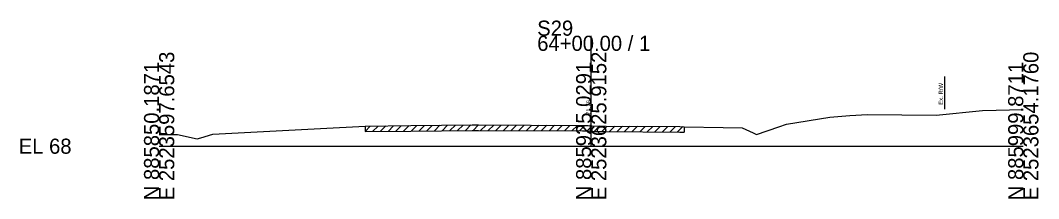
# Model space of a CAD drawing. Extents: x -26 to 163, y -10 to 4024.
# Drawn here: x -25.7 to 162.8, y 2990.3 to 3023.3 of the extents above; entities that cross this region are included whole.
import ezdxf

# ---------------------------------------------------------------- set-up
doc = ezdxf.new("R2010")
doc.units = 0
for name, color, linetype in [('RD_GPK_XS_Cell', 7, 'Continuous'), ('RD_XS_ExGround', 7, 'Continuous'), ('RD_XS_ExPaveRet', 7, 'Continuous'), ('RD_XS_ExRW', 7, 'Continuous'), ('RD_XS_TX_Elev_EX', 7, 'Continuous')]:
    doc.layers.add(name, color=color, linetype=linetype)

msp = doc.modelspace()

# ---------------------------------------------------------------- linework, layer by layer
at = {"layer": 'RD_GPK_XS_Cell'}
for p, q in [((80, 3000), (80, 3020.43)), ((0, 3000), (80, 3000)), ((80, 3000), (160, 3000))]:
    msp.add_line(p, q, dxfattribs=at)
at = {"layer": 'RD_XS_ExGround'}
for p, q in [((116.16, 3004.1), (124.21, 3005.35)), ((124.21, 3005.35), (127.89, 3005.69)), ((127.89, 3005.69), (131.15, 3005.84)), ((131.15, 3005.84), (143.87, 3005.72)), ((143.87, 3005.72), (152.42, 3006.61)), ((152.42, 3006.61), (160, 3006.81)), ((29.9, 3003.27), (38.13, 3003.69)), ((38.13, 3003.69), (46.62, 3003.8)), ((46.62, 3003.8), (57.97, 3003.93)), ((57.97, 3003.93), (59.13, 3003.93)), ((59.13, 3003.93), (78.42, 3003.85)), ((78.42, 3003.85), (79.46, 3003.84)), ((79.46, 3003.84), (79.89, 3003.76)), ((79.89, 3003.76), (80.2, 3003.75)), ((80.2, 3003.75), (82.68, 3003.73)), ((82.68, 3003.73), (96.43, 3003.62)), ((96.43, 3003.62), (97.21, 3003.61)), ((97.21, 3003.61), (104.44, 3003.49)), ((104.44, 3003.49), (107.92, 3003.4)), ((107.92, 3003.4), (110, 3002.45)), ((110.61, 3002.19), (114.74, 3003.6)), ((114.74, 3003.6), (116.16, 3004.1)), ((0, 3002.16), (1.97, 3002.17)), ((1.97, 3002.17), (2.28, 3002.18)), ((2.28, 3002.18), (3.4, 3002.18)), ((3.4, 3002.18), (7.06, 3001.36)), ((7.06, 3001.36), (7.7, 3001.52)), ((7.7, 3001.52), (9.96, 3002.21)), ((9.96, 3002.21), (29.9, 3003.27)), ((110, 3002.45), (110.61, 3002.19))]:
    msp.add_line(p, q, dxfattribs=at)
at = {"layer": 'RD_XS_ExPaveRet'}
for p, q in [((38.13, 3002.73), (39.1, 3003.71)), ((39.52, 3002.71), (40.54, 3003.73)), ((40.95, 3002.73), (41.97, 3003.74)), ((42.39, 3002.75), (43.4, 3003.76)), ((43.82, 3002.77), (44.83, 3003.78)), ((45.25, 3002.79), (46.27, 3003.8)), ((46.69, 3002.8), (47.7, 3003.82)), ((48.12, 3002.82), (49.13, 3003.83)), ((49.55, 3002.84), (50.56, 3003.85)), ((50.98, 3002.85), (51.99, 3003.87)), ((52.41, 3002.87), (53.42, 3003.88)), ((53.84, 3002.89), (54.85, 3003.9)), ((55.27, 3002.9), (56.28, 3003.92)), ((56.7, 3002.92), (57.71, 3003.93)), ((58.13, 3002.93), (59.12, 3003.93)), ((59.53, 3002.93), (60.53, 3003.92)), ((60.94, 3002.92), (61.94, 3003.92)), ((62.35, 3002.91), (63.35, 3003.91)), ((63.76, 3002.91), (64.76, 3003.9)), ((65.17, 3002.9), (66.16, 3003.9)), ((66.58, 3002.9), (67.57, 3003.89)), ((67.99, 3002.89), (68.98, 3003.89)), ((69.39, 3002.89), (70.39, 3003.88)), ((70.8, 3002.88), (71.8, 3003.88)), ((72.21, 3002.87), (73.21, 3003.87)), ((73.62, 3002.87), (74.62, 3003.86)), ((75.03, 3002.86), (76.02, 3003.86)), ((76.44, 3002.86), (77.43, 3003.85)), ((77.85, 3002.85), (78.84, 3003.85)), ((79.25, 3002.84), (80.16, 3003.75)), ((80.57, 3002.75), (81.56, 3003.74)), ((81.97, 3002.74), (82.97, 3003.73)), ((83.38, 3002.73), (84.37, 3003.72)), ((84.78, 3002.72), (85.77, 3003.71)), ((86.18, 3002.7), (87.18, 3003.7)), ((87.59, 3002.69), (88.58, 3003.69)), ((88.99, 3002.68), (89.98, 3003.67)), ((90.39, 3002.67), (91.38, 3003.66)), ((91.8, 3002.66), (92.79, 3003.65)), ((93.2, 3002.65), (94.19, 3003.64)), ((94.6, 3002.64), (95.59, 3003.63)), ((96, 3002.63), (96.99, 3003.62)), ((97.21, 3003.61), (97.21, 3002.61)), ((38.13, 3002.69), (46.63, 3002.8)), ((46.63, 3002.8), (57.97, 3002.93)), ((57.96, 3002.93), (59.12, 3002.93)), ((59.12, 3002.93), (78.42, 3002.85)), ((78.41, 3002.85), (79.37, 3002.84)), ((78.41, 3002.85), (78.42, 3002.85)), ((78.42, 3002.85), (78.42, 3002.85)), ((79.37, 3002.84), (79.78, 3002.77)), ((79.78, 3002.77), (80.18, 3002.75)), ((80.18, 3002.75), (82.67, 3002.73)), ((82.67, 3002.73), (96.42, 3002.62)), ((96.42, 3002.62), (97.21, 3002.61))]:
    msp.add_line(p, q, dxfattribs=at)
for points in [[(38.13, 3003.69), (38.13, 3002.69)], [(57.96, 3002.93), (57.96, 3002.93)], [(78.41, 3002.85), (78.41, 3002.85)], [(78.42, 3002.85), (78.42, 3002.85)]]:
    msp.add_lwpolyline(points, dxfattribs=at)
at = {"layer": 'RD_XS_ExRW'}
msp.add_line((145.39, 3012.88), (145.39, 3006.88), dxfattribs=at)

# ---------------------------------------------------------------- texts
at = {"layer": 'RD_GPK_XS_Cell'}
for s, p in [('S29', (70, 3020.43)), ('64+00.00 / 1', (70, 3017.63)), ('EL 68', (-26, 2998.6))]:
    msp.add_text(s, height=2.8, dxfattribs=at).set_placement(p)
for s, p in [('E 2523597.6543', (2.8, 2990)), ('E 2523625.9152', (82.8, 2990)), ('E 2523654.1760', (162.8, 2990)), ('N 885850.1871', (0, 2990)), ('N 885925.0291', (80, 2990)), ('N 885999.8711', (160, 2990))]:
    msp.add_text(s, height=2.8, rotation=90, dxfattribs=at).set_placement(p)
at = {"layer": 'RD_XS_ExRW'}
msp.add_text('Ex. R/W ', height=0.8, rotation=90, dxfattribs=at).set_placement((145.14, 3007.66))
at = {"layer": 'RD_XS_TX_Elev_EX'}
msp.add_text('71.76', height=0.8, rotation=90, dxfattribs=at).set_placement((79.9, 3005.76))

doc.saveas('drawing.dxf')
